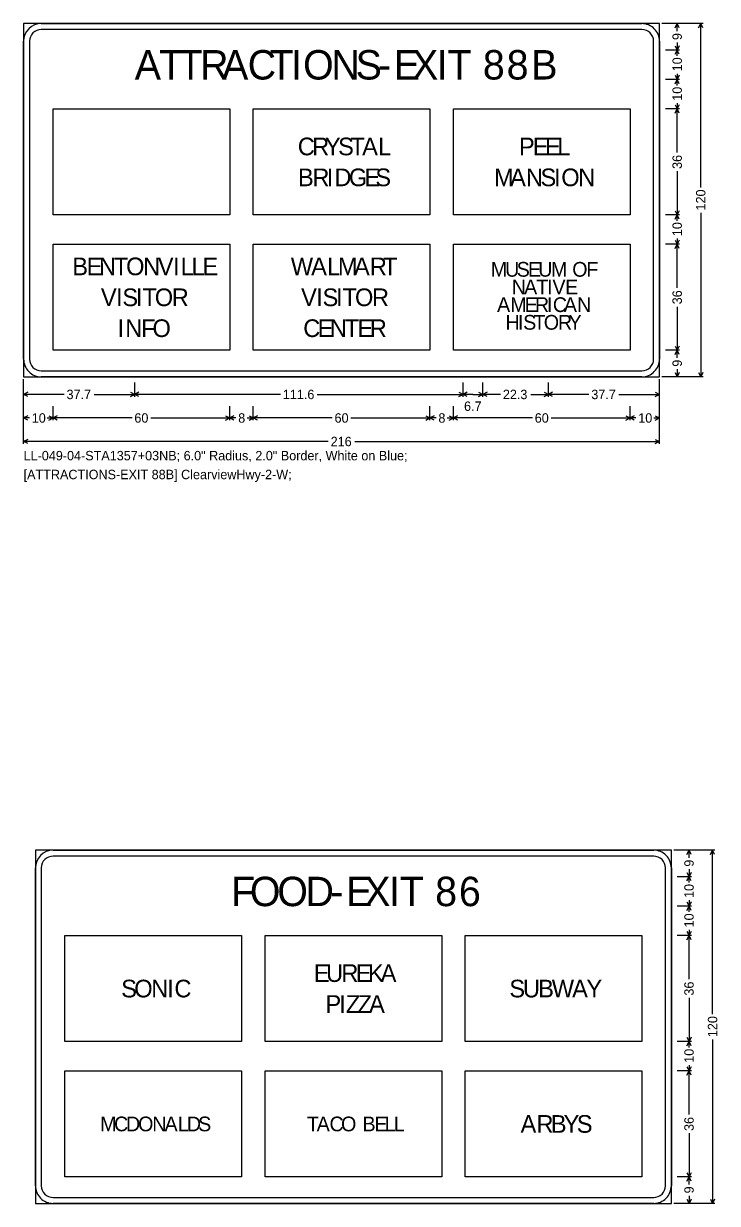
# Model space of a CAD drawing. Extents: x 667331 to 731245, y 738830 to 753817.
# Drawn here: x 720723 to 721076, y 743804 to 744406 of the extents above; entities that cross this region are included whole.
import ezdxf

# ---------------------------------------------------------------- set-up
doc = ezdxf.new("R2010")
doc.units = 0
doc.layers.add('R_SIGN', color=7, linetype='Continuous')

msp = doc.modelspace()

# ---------------------------------------------------------------- linework, layer by layer
at = {"layer": 'R_SIGN'}
for p, q in [((721069.01, 744405.66), (721048.01, 744405.66)), ((721057.01, 744405.66), (721049.81, 744405.66)), ((721054.74, 744403.51), (721055.81, 744405.66)), ((721055.81, 744401.76), (721055.81, 744405.66)), ((721056.89, 744403.51), (721055.81, 744405.66)), ((721066.74, 744403.51), (721067.81, 744405.66)), ((721067.81, 744322.11), (721067.81, 744405.66)), ((721068.89, 744403.51), (721067.81, 744405.66)), ((721057.01, 744392.16), (721049.81, 744392.16)), ((721054.74, 744394.31), (721055.81, 744392.16)), ((721054.74, 744390.01), (721055.81, 744392.16)), ((721055.81, 744396.07), (721055.81, 744392.16)), ((721056.89, 744394.31), (721055.81, 744392.16)), ((721055.81, 744389.19), (721055.81, 744392.16)), ((721056.89, 744390.01), (721055.81, 744392.16)), ((721054.74, 744379.31), (721055.81, 744377.16)), ((721055.81, 744380.13), (721055.81, 744377.16)), ((721056.89, 744379.31), (721055.81, 744377.16)), ((721057.01, 744377.16), (721049.81, 744377.16)), ((721054.74, 744375.01), (721055.81, 744377.16)), ((721055.81, 744374.19), (721055.81, 744377.16)), ((721056.89, 744375.01), (721055.81, 744377.16)), ((720737.81, 744308.16), (720737.81, 744362.16)), ((720737.81, 744362.16), (720827.81, 744362.16)), ((720827.81, 744362.16), (720827.81, 744308.16)), ((720839.81, 744308.16), (720839.81, 744362.16)), ((720839.81, 744362.16), (720929.81, 744362.16)), ((720929.81, 744362.16), (720929.81, 744308.16)), ((720941.81, 744308.16), (720941.81, 744362.16)), ((720941.81, 744362.16), (721031.81, 744362.16)), ((721031.81, 744362.16), (721031.81, 744308.16)), ((721057.01, 744362.16), (721049.81, 744362.16)), ((721054.74, 744364.31), (721055.81, 744362.16)), ((721054.74, 744360.01), (721055.81, 744362.16)), ((721055.81, 744365.13), (721055.81, 744362.16)), ((721056.89, 744364.31), (721055.81, 744362.16)), ((721055.81, 744339.94), (721055.81, 744362.16)), ((721056.89, 744360.01), (721055.81, 744362.16)), ((721055.81, 744330.38), (721055.81, 744308.16)), ((720827.81, 744308.16), (720737.81, 744308.16)), ((720929.81, 744308.16), (720839.81, 744308.16)), ((721031.81, 744308.16), (720941.81, 744308.16)), ((721057.01, 744308.16), (721049.81, 744308.16)), ((721054.74, 744310.31), (721055.81, 744308.16)), ((721054.74, 744306.01), (721055.81, 744308.16)), ((721056.89, 744310.31), (721055.81, 744308.16)), ((721055.81, 744305.19), (721055.81, 744308.16)), ((721056.89, 744306.01), (721055.81, 744308.16)), ((721067.81, 744309.21), (721067.81, 744225.66)), ((721054.74, 744295.31), (721055.81, 744293.16)), ((721055.81, 744296.13), (721055.81, 744293.16)), ((721056.89, 744295.31), (721055.81, 744293.16)), ((720737.81, 744239.16), (720737.81, 744293.16)), ((720737.81, 744293.16), (720827.81, 744293.16)), ((720827.81, 744293.16), (720827.81, 744239.16)), ((720839.81, 744239.16), (720839.81, 744293.16)), ((720839.81, 744293.16), (720929.81, 744293.16)), ((720929.81, 744293.16), (720929.81, 744239.16)), ((720941.81, 744239.16), (720941.81, 744293.16)), ((720941.81, 744293.16), (721031.81, 744293.16)), ((721031.81, 744293.16), (721031.81, 744239.16)), ((721057.01, 744293.16), (721049.81, 744293.16)), ((721054.74, 744291.01), (721055.81, 744293.16)), ((721055.81, 744270.94), (721055.81, 744293.16)), ((721056.89, 744291.01), (721055.81, 744293.16)), ((721055.81, 744261.38), (721055.81, 744239.16)), ((721054.74, 744241.31), (721055.81, 744239.16)), ((721056.89, 744241.31), (721055.81, 744239.16)), ((720827.81, 744239.16), (720737.81, 744239.16)), ((720929.81, 744239.16), (720839.81, 744239.16)), ((721031.81, 744239.16), (720941.81, 744239.16)), ((721057.01, 744239.16), (721049.81, 744239.16)), ((721057.01, 744239.16), (721049.81, 744239.16)), ((721054.74, 744237.01), (721055.81, 744239.16)), ((721055.81, 744235.26), (721055.81, 744239.16)), ((721056.89, 744237.01), (721055.81, 744239.16)), ((721055.81, 744229.57), (721055.81, 744225.66)), ((720722.81, 744191.46), (720722.81, 744224.46)), ((720722.81, 744215.46), (720722.81, 744222.66)), ((720779.43, 744215.46), (720779.43, 744222.66)), ((720946.72, 744215.46), (720946.72, 744222.66)), ((720956.81, 744215.46), (720956.81, 744222.66)), ((720990.2, 744215.46), (720990.2, 744222.66)), ((720990.2, 744215.46), (720990.2, 744222.66)), ((721046.81, 744191.46), (721046.81, 744224.46)), ((721046.81, 744215.46), (721046.81, 744222.66)), ((721069.01, 744225.66), (721048.01, 744225.66)), ((721057.01, 744225.66), (721049.81, 744225.66)), ((721054.74, 744227.81), (721055.81, 744225.66)), ((721056.89, 744227.81), (721055.81, 744225.66)), ((721066.74, 744227.81), (721067.81, 744225.66)), ((721068.89, 744227.81), (721067.81, 744225.66)), ((720724.96, 744217.73), (720722.81, 744216.66)), ((720743.49, 744216.66), (720722.81, 744216.66)), ((720724.96, 744215.59), (720722.81, 744216.66)), ((720758.76, 744216.66), (720779.43, 744216.66)), ((720777.29, 744217.73), (720779.43, 744216.66)), ((720777.29, 744215.59), (720779.43, 744216.66)), ((720781.58, 744217.73), (720779.43, 744216.66)), ((720853.7, 744216.66), (720779.43, 744216.66)), ((720781.58, 744215.59), (720779.43, 744216.66)), ((720872.46, 744216.66), (720946.72, 744216.66)), ((720944.57, 744217.73), (720946.72, 744216.66)), ((720944.57, 744215.59), (720946.72, 744216.66)), ((720948.87, 744217.73), (720946.72, 744216.66)), ((720951.76, 744216.66), (720946.72, 744216.66)), ((720948.87, 744215.59), (720946.72, 744216.66)), ((720951.76, 744216.66), (720956.81, 744216.66)), ((720954.66, 744217.73), (720956.81, 744216.66)), ((720954.66, 744215.59), (720956.81, 744216.66)), ((720958.95, 744217.73), (720956.81, 744216.66)), ((720965.8, 744216.66), (720956.81, 744216.66)), ((720958.95, 744215.59), (720956.81, 744216.66)), ((720981.2, 744216.66), (720990.2, 744216.66)), ((720988.05, 744217.73), (720990.2, 744216.66)), ((720988.05, 744215.59), (720990.2, 744216.66)), ((720992.34, 744217.73), (720990.2, 744216.66)), ((721010.87, 744216.66), (720990.2, 744216.66)), ((720992.34, 744215.59), (720990.2, 744216.66)), ((721026.14, 744216.66), (721046.81, 744216.66)), ((721044.67, 744217.73), (721046.81, 744216.66)), ((721044.67, 744215.59), (721046.81, 744216.66)), ((720722.81, 744203.46), (720722.81, 744210.66)), ((720737.81, 744203.46), (720737.81, 744210.66)), ((720827.81, 744203.46), (720827.81, 744210.66)), ((720839.81, 744203.46), (720839.81, 744210.66)), ((720929.81, 744203.46), (720929.81, 744210.66)), ((720941.81, 744203.46), (720941.81, 744210.66)), ((721031.81, 744203.46), (721031.81, 744210.66)), ((721031.81, 744203.46), (721031.81, 744210.66)), ((721046.81, 744203.46), (721046.81, 744210.66)), ((720724.96, 744205.73), (720722.81, 744204.66)), ((720725.78, 744204.66), (720722.81, 744204.66)), ((720724.96, 744203.59), (720722.81, 744204.66)), ((720734.84, 744204.66), (720737.81, 744204.66)), ((720735.67, 744205.73), (720737.81, 744204.66)), ((720735.67, 744203.59), (720737.81, 744204.66)), ((720739.96, 744205.73), (720737.81, 744204.66)), ((720778.05, 744204.66), (720737.81, 744204.66)), ((720739.96, 744203.59), (720737.81, 744204.66)), ((720787.58, 744204.66), (720827.81, 744204.66)), ((720825.67, 744205.73), (720827.81, 744204.66)), ((720825.67, 744203.59), (720827.81, 744204.66)), ((720829.96, 744205.73), (720827.81, 744204.66)), ((720830.96, 744204.66), (720827.81, 744204.66)), ((720829.96, 744203.59), (720827.81, 744204.66)), ((720836.67, 744204.66), (720839.81, 744204.66)), ((720837.67, 744205.73), (720839.81, 744204.66)), ((720837.67, 744203.59), (720839.81, 744204.66)), ((720841.96, 744205.73), (720839.81, 744204.66)), ((720880.05, 744204.66), (720839.81, 744204.66)), ((720841.96, 744203.59), (720839.81, 744204.66)), ((720889.58, 744204.66), (720929.81, 744204.66)), ((720927.67, 744205.73), (720929.81, 744204.66)), ((720927.67, 744203.59), (720929.81, 744204.66)), ((720931.96, 744205.73), (720929.81, 744204.66)), ((720932.96, 744204.66), (720929.81, 744204.66)), ((720931.96, 744203.59), (720929.81, 744204.66)), ((720938.67, 744204.66), (720941.81, 744204.66)), ((720939.67, 744205.73), (720941.81, 744204.66)), ((720939.67, 744203.59), (720941.81, 744204.66)), ((720943.96, 744205.73), (720941.81, 744204.66)), ((720982.05, 744204.66), (720941.81, 744204.66)), ((720943.96, 744203.59), (720941.81, 744204.66)), ((720991.58, 744204.66), (721031.81, 744204.66)), ((721029.67, 744205.73), (721031.81, 744204.66)), ((721029.67, 744203.59), (721031.81, 744204.66)), ((721033.96, 744205.73), (721031.81, 744204.66)), ((721034.78, 744204.66), (721031.81, 744204.66)), ((721033.96, 744203.59), (721031.81, 744204.66)), ((721043.84, 744204.66), (721046.81, 744204.66)), ((721044.67, 744205.73), (721046.81, 744204.66)), ((721044.67, 744203.59), (721046.81, 744204.66)), ((720724.96, 744193.73), (720722.81, 744192.66)), ((720878.06, 744192.66), (720722.81, 744192.66)), ((720724.96, 744191.59), (720722.81, 744192.66)), ((720891.57, 744192.66), (721046.81, 744192.66)), ((721044.67, 744193.73), (721046.81, 744192.66)), ((721044.67, 744191.59), (721046.81, 744192.66)), ((721075.04, 743984.34), (721054.04, 743984.34)), ((721063.04, 743984.34), (721055.84, 743984.34)), ((721060.77, 743982.2), (721061.84, 743984.34)), ((721061.84, 743980.44), (721061.84, 743984.34)), ((721062.91, 743982.2), (721061.84, 743984.34)), ((721072.77, 743982.2), (721073.84, 743984.34)), ((721073.84, 743900.79), (721073.84, 743984.34)), ((721074.91, 743982.2), (721073.84, 743984.34)), ((721063.04, 743970.84), (721055.84, 743970.84)), ((721060.77, 743972.99), (721061.84, 743970.84)), ((721060.77, 743968.7), (721061.84, 743970.84)), ((721061.84, 743974.75), (721061.84, 743970.84)), ((721062.91, 743972.99), (721061.84, 743970.84)), ((721061.84, 743967.87), (721061.84, 743970.84)), ((721062.91, 743968.7), (721061.84, 743970.84)), ((721060.77, 743957.99), (721061.84, 743955.84)), ((721061.84, 743958.81), (721061.84, 743955.84)), ((721062.91, 743957.99), (721061.84, 743955.84)), ((721063.04, 743955.84), (721055.84, 743955.84)), ((721060.77, 743953.7), (721061.84, 743955.84)), ((721061.84, 743952.87), (721061.84, 743955.84)), ((721062.91, 743953.7), (721061.84, 743955.84)), ((720743.84, 743886.84), (720743.84, 743940.84)), ((720743.84, 743940.84), (720833.84, 743940.84)), ((720833.84, 743940.84), (720833.84, 743886.84)), ((720845.84, 743886.84), (720845.84, 743940.84)), ((720845.84, 743940.84), (720935.84, 743940.84)), ((720935.84, 743940.84), (720935.84, 743886.84)), ((720947.84, 743886.84), (720947.84, 743940.84)), ((720947.84, 743940.84), (721037.84, 743940.84)), ((721037.84, 743940.84), (721037.84, 743886.84)), ((721063.04, 743940.84), (721055.84, 743940.84)), ((721060.77, 743942.99), (721061.84, 743940.84)), ((721060.77, 743938.7), (721061.84, 743940.84)), ((721061.84, 743943.81), (721061.84, 743940.84)), ((721062.91, 743942.99), (721061.84, 743940.84)), ((721061.84, 743918.62), (721061.84, 743940.84)), ((721062.91, 743938.7), (721061.84, 743940.84)), ((721061.84, 743909.06), (721061.84, 743886.84)), ((720833.84, 743886.84), (720743.84, 743886.84)), ((720935.84, 743886.84), (720845.84, 743886.84)), ((721037.84, 743886.84), (720947.84, 743886.84)), ((721063.04, 743886.84), (721055.84, 743886.84)), ((721060.77, 743888.99), (721061.84, 743886.84)), ((721060.77, 743884.7), (721061.84, 743886.84)), ((721062.91, 743888.99), (721061.84, 743886.84)), ((721061.84, 743883.87), (721061.84, 743886.84)), ((721062.91, 743884.7), (721061.84, 743886.84)), ((721073.84, 743887.89), (721073.84, 743804.34)), ((721060.77, 743873.99), (721061.84, 743871.84)), ((721061.84, 743874.81), (721061.84, 743871.84)), ((721062.91, 743873.99), (721061.84, 743871.84)), ((720743.84, 743817.84), (720743.84, 743871.84)), ((720743.84, 743871.84), (720833.84, 743871.84)), ((720833.84, 743871.84), (720833.84, 743817.84)), ((720845.84, 743817.84), (720845.84, 743871.84)), ((720845.84, 743871.84), (720935.84, 743871.84)), ((720935.84, 743871.84), (720935.84, 743817.84)), ((720947.84, 743817.84), (720947.84, 743871.84)), ((720947.84, 743871.84), (721037.84, 743871.84)), ((721037.84, 743871.84), (721037.84, 743817.84)), ((721063.04, 743871.84), (721055.84, 743871.84)), ((721060.77, 743869.7), (721061.84, 743871.84)), ((721061.84, 743849.62), (721061.84, 743871.84)), ((721062.91, 743869.7), (721061.84, 743871.84)), ((721061.84, 743840.06), (721061.84, 743817.84)), ((721060.77, 743819.99), (721061.84, 743817.84)), ((721062.91, 743819.99), (721061.84, 743817.84)), ((720833.84, 743817.84), (720743.84, 743817.84)), ((720935.84, 743817.84), (720845.84, 743817.84)), ((721037.84, 743817.84), (720947.84, 743817.84)), ((721063.04, 743817.84), (721055.84, 743817.84)), ((721063.04, 743817.84), (721055.84, 743817.84)), ((721060.77, 743815.7), (721061.84, 743817.84)), ((721061.84, 743813.94), (721061.84, 743817.84)), ((721062.91, 743815.7), (721061.84, 743817.84)), ((721061.84, 743808.25), (721061.84, 743804.34)), ((721075.04, 743804.34), (721054.04, 743804.34)), ((721063.04, 743804.34), (721055.84, 743804.34)), ((721060.77, 743806.49), (721061.84, 743804.34)), ((721062.91, 743806.49), (721061.84, 743804.34)), ((721072.77, 743806.49), (721073.84, 743804.34)), ((721074.91, 743806.49), (721073.84, 743804.34))]:
    msp.add_line(p, q, dxfattribs=at)
for points in [[(720722.81, 744225.66), (721046.81, 744225.66), (721046.81, 744405.66), (720722.81, 744405.66), (720722.81, 744225.66), (720722.81, 744225.66)], [(720731.81, 744405.66), (721037.81, 744405.66)], [(721037.81, 744402.66), (720731.81, 744402.66)], [(720722.81, 744234.66), (720722.81, 744396.66)], [(720725.81, 744396.66), (720725.81, 744234.66)], [(721043.81, 744234.66), (721043.81, 744396.66)], [(721046.81, 744396.66), (721046.81, 744234.66)], [(720731.81, 744228.66), (721037.81, 744228.66)], [(721037.81, 744225.66), (720731.81, 744225.66)], [(720728.84, 743804.34), (721052.84, 743804.34), (721052.84, 743984.34), (720728.84, 743984.34), (720728.84, 743804.34), (720728.84, 743804.34)], [(720737.84, 743984.34), (721043.84, 743984.34)], [(721043.84, 743981.34), (720737.84, 743981.34)], [(720728.84, 743813.34), (720728.84, 743975.34)], [(720731.84, 743975.34), (720731.84, 743813.34)], [(721049.84, 743813.34), (721049.84, 743975.34)], [(721052.84, 743975.34), (721052.84, 743813.34)], [(720737.84, 743807.34), (721043.84, 743807.34)], [(721043.84, 743804.34), (720737.84, 743804.34)]]:
    msp.add_lwpolyline(points, dxfattribs=at)
for centre, radius, start, end in [((720731.81, 744396.66), 9, 90.00021, 179.99985), ((721037.81, 744396.66), 9, 0, 90.00021), ((720731.81, 744396.66), 6, 90.00021, 179.99985), ((721037.81, 744396.66), 6, 0, 90.00021), ((720731.81, 744234.66), 9, 179.99985, 270.00006), ((720731.81, 744234.66), 6, 179.99985, 270.00006), ((721037.81, 744234.66), 9, 270.00006, 0.00027), ((721037.81, 744234.66), 6, 270.00006, 0.00027), ((720737.84, 743975.34), 9, 90.00021, 179.99985), ((721043.84, 743975.34), 9, 0, 90.00021), ((720737.84, 743975.34), 6, 90.00021, 179.99985), ((721043.84, 743975.34), 6, 0, 90.00021), ((720737.84, 743813.34), 9, 179.99985, 270.00006), ((720737.84, 743813.34), 6, 179.99985, 270.00006), ((721043.84, 743813.34), 9, 270.00006, 0.00027), ((721043.84, 743813.34), 6, 270.00006, 0.00027)]:
    msp.add_arc(centre, radius, start, end, dxfattribs=at)

# ---------------------------------------------------------------- texts
for s, p in [('9', (721058.21, 744397.27)), ('10', (721058.21, 744381.33)), ('10', (721058.21, 744366.33)), ('36', (721058.21, 744331.58)), ('120', (721070.21, 744310.41)), ('10', (721058.21, 744297.33)), ('36', (721058.21, 744262.58)), ('9', (721058.21, 744230.77)), ('9', (721064.24, 743975.95)), ('10', (721064.24, 743960.01)), ('10', (721064.24, 743945.01)), ('36', (721064.24, 743910.26)), ('120', (721076.24, 743889.09)), ('10', (721064.24, 743876.01)), ('36', (721064.24, 743841.26)), ('9', (721064.24, 743809.45))]:
    msp.add_text(s, height=4.8, rotation=90.00021, dxfattribs=at).set_placement(p)
for s, height, p in [('A', 15, (720779.43, 744377.16)), ('T', 15, (720791.89, 744377.16)), ('T', 15, (720801.81, 744377.16)), ('R', 15, (720812.74, 744377.16)), ('A', 15, (720823.93, 744377.16)), ('C', 15, (720836.98, 744377.16)), ('T', 15, (720848.16, 744377.16)), ('I', 15, (720859.09, 744377.16)), ('O', 15, (720865.2, 744377.16)), ('N', 15, (720879.6, 744377.16)), ('S', 15, (720891.98, 744377.16)), ('E', 15, (720911.47, 744377.16)), ('X', 15, (720920.71, 744377.16)), ('I', 15, (720933.33, 744377.16)), ('T', 15, (720938.84, 744377.16)), ('8', 15, (720956.81, 744377.16)), ('8', 15, (720968.92, 744377.16)), ('B', 15, (720981.47, 744377.16)), ('-', 15, (720903.42, 744377.16)), ('C', 9, (720862.52, 744338.54)), ('R', 9, (720869.84, 744338.54)), ('Y', 9, (720876.35, 744338.54)), ('S', 9, (720883.06, 744338.54)), ('T', 9, (720889.37, 744338.54)), ('A', 9, (720895.31, 744338.54)), ('L', 9, (720903.4, 744338.54)), ('P', 9, (720975.2, 744338.54)), ('E', 9, (720982.21, 744338.54)), ('E', 9, (720988.47, 744338.54)), ('L', 9, (720994.72, 744338.54)), ('B', 9, (720862.62, 744322.79)), ('R', 9, (720869.94, 744322.79)), ('I', 9, (720877.26, 744322.79)), ('D', 9, (720881.18, 744322.79)), ('G', 9, (720888.55, 744322.79)), ('E', 9, (720896.48, 744322.79)), ('S', 9, (720902.03, 744322.79)), ('M', 9, (720962.48, 744322.79)), ('A', 9, (720970.67, 744322.79)), ('N', 9, (720978.76, 744322.79)), ('S', 9, (720986.18, 744322.79)), ('I', 9, (720993.09, 744322.79)), ('O', 9, (720996.76, 744322.79)), ('N', 9, (721005.4, 744322.79)), ('B', 9, (720747.63, 744277.41)), ('E', 9, (720754.95, 744277.41)), ('N', 9, (720761.2, 744277.41)), ('T', 9, (720768.73, 744277.41)), ('O', 9, (720775.04, 744277.41)), ('N', 9, (720783.68, 744277.41)), ('V', 9, (720791.2, 744277.41)), ('I', 9, (720798.93, 744277.41)), ('L', 9, (720802.85, 744277.41)), ('L', 9, (720808.39, 744277.41)), ('E', 9, (720813.93, 744277.41)), ('W', 9, (720858.96, 744277.41)), ('A', 9, (720869.33, 744277.41)), ('L', 9, (720877.42, 744277.41)), ('M', 9, (720882.96, 744277.41)), ('A', 9, (720891.14, 744277.41)), ('R', 9, (720899.23, 744277.41)), ('T', 9, (720905.94, 744277.41)), ('M', 7.5, (720960.82, 744276.66)), ('U', 7.5, (720968.15, 744276.66)), ('S', 7.5, (720974.04, 744276.66)), ('E', 7.5, (720979.8, 744276.66)), ('U', 7.5, (720985.01, 744276.66)), ('M', 7.5, (720991.5, 744276.66)), ('O', 7.5, (721002.34, 744276.66)), ('F', 7.5, (721009.55, 744276.66)), ('V', 9, (720762.2, 744261.66)), ('I', 9, (720769.93, 744261.66)), ('S', 9, (720773.13, 744261.66)), ('I', 9, (720780.04, 744261.66)), ('T', 9, (720783.35, 744261.66)), ('O', 9, (720789.65, 744261.66)), ('R', 9, (720798.3, 744261.66)), ('V', 9, (720864.2, 744261.66)), ('I', 9, (720871.93, 744261.66)), ('S', 9, (720875.13, 744261.66)), ('I', 9, (720882.04, 744261.66)), ('T', 9, (720885.35, 744261.66)), ('O', 9, (720891.65, 744261.66)), ('R', 9, (720900.3, 744261.66)), ('N', 7.5, (720971.54, 744267.66)), ('A', 7.5, (720977.81, 744267.66)), ('T', 7.5, (720984.04, 744267.66)), ('I', 7.5, (720989.51, 744267.66)), ('V', 7.5, (720992.26, 744267.66)), ('E', 7.5, (720998.7, 744267.66)), ('A', 7.5, (720964.04, 744258.66)), ('M', 7.5, (720970.78, 744258.66)), ('E', 7.5, (720978.11, 744258.66)), ('R', 7.5, (720983.32, 744258.66)), ('I', 7.5, (720989.42, 744258.66)), ('C', 7.5, (720992.47, 744258.66)), ('A', 7.5, (720998.06, 744258.66)), ('N', 7.5, (721004.8, 744258.66)), ('I', 9, (720770.69, 744245.91)), ('N', 9, (720774.6, 744245.91)), ('F', 9, (720782.74, 744245.91)), ('O', 9, (720788.48, 744245.91)), ('C', 9, (720865.29, 744245.91)), ('E', 9, (720872.61, 744245.91)), ('N', 9, (720878.87, 744245.91)), ('T', 9, (720886.39, 744245.91)), ('E', 9, (720892.95, 744245.91)), ('R', 9, (720899.2, 744245.91)), ('H', 7.5, (720968.32, 744249.66)), ('I', 7.5, (720974.68, 744249.66)), ('S', 7.5, (720977.34, 744249.66)), ('T', 7.5, (720982.6, 744249.66)), ('O', 7.5, (720987.85, 744249.66)), ('R', 7.5, (720995.06, 744249.66)), ('Y', 7.5, (721000.48, 744249.66)), ('37.7', 4.8, (720744.69, 744214.26)), ('111.6', 4.8, (720854.9, 744214.26)), ('22.3', 4.8, (720967, 744214.26)), ('37.7', 4.8, (721012.07, 744214.26)), ('6.7', 4.8, (720947.23, 744208.26)), ('10', 4.8, (720726.98, 744202.26)), ('60', 4.8, (720779.25, 744202.26)), ('8', 4.8, (720832.16, 744202.26)), ('60', 4.8, (720881.25, 744202.26)), ('8', 4.8, (720934.16, 744202.26)), ('60', 4.8, (720983.25, 744202.26)), ('10', 4.8, (721035.98, 744202.26)), ('216', 4.8, (720879.26, 744190.26)), ('LL-049-04-STA1357+03NB; 6.0" Radius, 2.0" Border, White on Blue; ', 4.8, (720722.81, 744183.06)), ('[ATTRACTIONS-EXIT 88B] ClearviewHwy-2-W; ', 4.8, (720722.81, 744173.46)), ('F', 15, (720828.51, 743955.84)), ('O', 15, (720838.09, 743955.84)), ('O', 15, (720852.07, 743955.84)), ('D', 15, (720866.47, 743955.84)), ('E', 15, (720887.15, 743955.84)), ('X', 15, (720896.39, 743955.84)), ('I', 15, (720909.02, 743955.84)), ('T', 15, (720914.53, 743955.84)), ('8', 15, (720932.49, 743955.84)), ('6', 15, (720944.61, 743955.84)), ('-', 15, (720879.1, 743955.84)), ('E', 9, (720870.68, 743917.22)), ('U', 9, (720876.93, 743917.22)), ('R', 9, (720884.71, 743917.22)), ('E', 9, (720892.03, 743917.22)), ('K', 9, (720898.29, 743917.22)), ('A', 9, (720904.75, 743917.22)), ('S', 9, (720772.54, 743909.34)), ('O', 9, (720779.2, 743909.34)), ('N', 9, (720787.85, 743909.34)), ('I', 9, (720795.98, 743909.34)), ('C', 9, (720799.64, 743909.34)), ('S', 9, (720970.31, 743909.34)), ('U', 9, (720977.23, 743909.34)), ('B', 9, (720985.01, 743909.34)), ('W', 9, (720991.92, 743909.34)), ('A', 9, (721002.3, 743909.34)), ('Y', 9, (721009.57, 743909.34)), ('P', 9, (720876.6, 743901.47)), ('I', 9, (720883.62, 743901.47)), ('Z', 9, (720887.03, 743901.47)), ('Z', 9, (720892.98, 743901.47)), ('A', 9, (720898.82, 743901.47)), ('M', 7.5, (720761.78, 743841.09)), ('C', 7.5, (720768.9, 743841.09)), ('D', 7.5, (720775, 743841.09)), ('O', 7.5, (720781.15, 743841.09)), ('N', 7.5, (720788.35, 743841.09)), ('A', 7.5, (720794.62, 743841.09)), ('L', 7.5, (720801.36, 743841.09)), ('D', 7.5, (720805.98, 743841.09)), ('S', 7.5, (720811.74, 743841.09)), ('T', 7.5, (720867.17, 743841.09)), ('A', 7.5, (720872.13, 743841.09)), ('C', 7.5, (720878.66, 743841.09)), ('O', 7.5, (720884.55, 743841.09)), ('B', 7.5, (720895.48, 743841.09)), ('E', 7.5, (720901.58, 743841.09)), ('L', 7.5, (720906.79, 743841.09)), ('L', 7.5, (720911.41, 743841.09)), ('A', 9, (720976.03, 743840.34)), ('R', 9, (720984.12, 743840.34)), ('B', 9, (720991.44, 743840.34)), ('Y', 9, (720997.95, 743840.34)), ('S', 9, (721004.66, 743840.34))]:
    msp.add_text(s, height=height, dxfattribs=at).set_placement(p)

doc.saveas('drawing.dxf')
